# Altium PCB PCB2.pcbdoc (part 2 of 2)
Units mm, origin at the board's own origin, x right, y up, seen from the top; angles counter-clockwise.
Board outline 201.42 x 135 mm, 2 copper layers (Top Layer, Bottom Layer); 117 components, 69 nets, 446 pads, 480 vias.
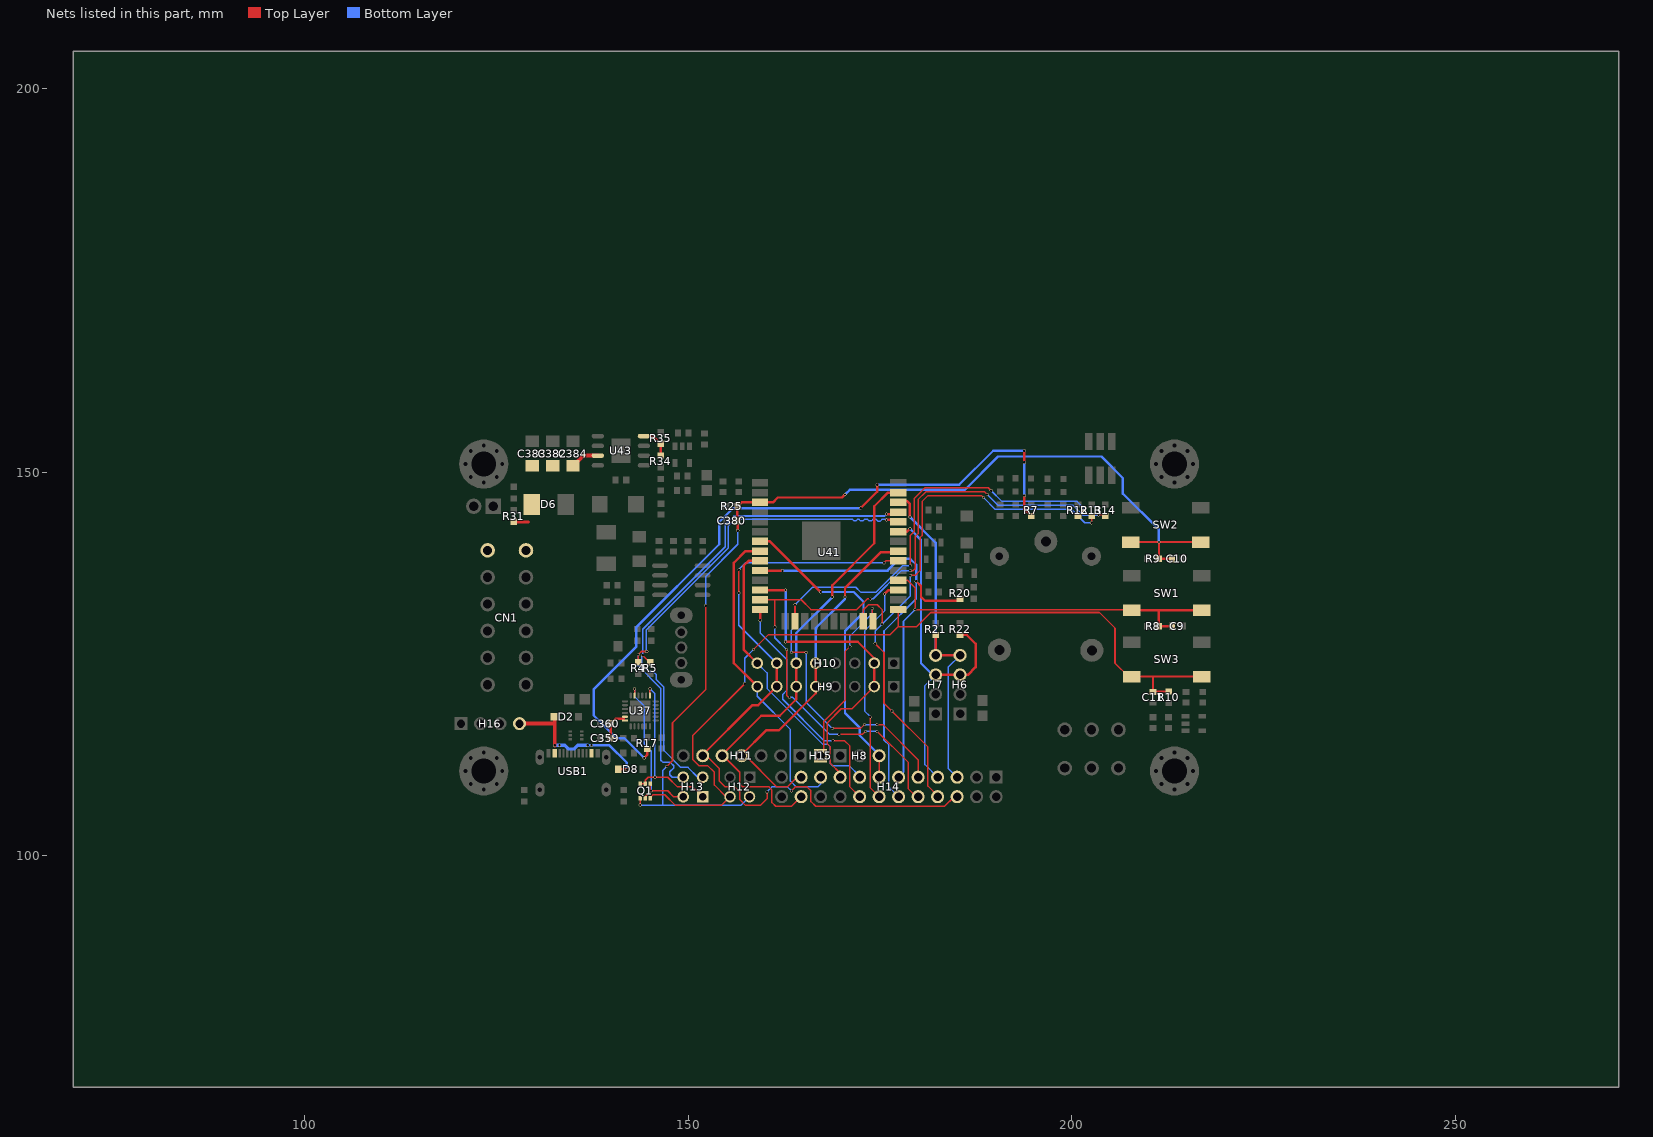
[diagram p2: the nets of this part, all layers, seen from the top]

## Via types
v1: diameter 0.4, hole 0.3, Top Layer to Bottom Layer, 480 vias

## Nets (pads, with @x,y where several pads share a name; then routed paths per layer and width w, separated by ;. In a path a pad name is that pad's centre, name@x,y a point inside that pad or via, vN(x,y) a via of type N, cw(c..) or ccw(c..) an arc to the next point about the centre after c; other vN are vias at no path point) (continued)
DTR: H13.2 Q1.1 Q1.5 U37.23 | length 21.9
  Top Layer w0.2: U37.23@143.014,120.872 v1(143.014,121.761) ; Q1.5@144.399,107.508 144.399,107.696 v1(145.161,108.458) ; Q1.1@145.049,109.408 145.049,108.458 v1(145.161,108.458) ; H13.2@149.352,107.696 148.082,107.696 147.32,108.458 v1(145.161,108.458)
  Bottom Layer w0.2: v1(143.014,121.761) 143.014,120.765 144.272,119.507 144.272,114.554 145.161,113.665 v1(145.161,108.458)
EN: C10.1 C380.1 H12.2 Q1.4 R9.1 R25.2 SW2.3 SW2.4 U41.3 | length 136.1
  Top Layer w0.2: v1(143.749,106.619) Q1.4@143.749,107.508 ; v1(147.193,111.633) 147.955,112.395 147.955,117.348 152.273,121.666 v1(152.273,132.588)
  Top Layer w0.312: v1(156.453,142.367) 156.453,143.586 C380.1@156.402,143.637 156.402,145.489 R25.2@156.455,145.542 156.961,146.048 U41.3@159.364,146.048 161.034,146.048 161.671,146.685 170.055,146.685 v1(170.434,147.064) ; SW2.3@207.667,140.879 v1(211.346,140.879) ; C10.1@213.041,138.684 R9.1@211.319,138.684 211.346,138.71 v1(211.346,140.879) ; SW2.4@216.767,140.879 v1(211.346,140.879)
  Bottom Layer w0.2: v1(143.749,106.619) 143.815,106.553 146.671,106.553 ; v1(147.193,111.633) 146.671,111.111 146.671,106.553 ; v1(152.273,132.588) 152.273,136.398 156.453,140.578 v1(156.453,142.367) ; H12.2@157.988,107.696 156.845,106.553 146.671,106.553
  Bottom Layer w0.312: v1(170.434,147.064) 171.071,147.701 186.055,147.701 190.373,152.019 203.835,152.019 206.629,149.225 206.629,147.193 211.328,142.494 v1@211.328,140.843
FB: R34.2 R35.1 U43.4 | length 4.2
  Top Layer w0.312: U43.4@144.224,154.686 145.424,154.686 R35.1@146.431,153.679 R34.2@146.431,152.137
GND: 
IO0: C11.1 H12.4 Q1.6 R10.1 SW3.3 SW3.4 U41.25 | length 109.9
  Top Layer w0.2: Q1.6@145.049,107.508 145.049,107.584 145.415,107.95 146.939,107.95 148.336,106.553 154.305,106.553 H12.4@155.448,107.696 154.94,107.696 153.416,109.22 153.416,110.871 152.527,111.76 151.384,111.76 150.622,112.522 150.622,115.697 v1(157.353,122.428) ; v1(158.496,126.873) 160.401,128.778 176.276,128.778 177.364,129.866 ; U41.25@177.364,132.078 177.364,129.866 ; SW3.3@207.794,123.353 207.355,123.353 205.613,125.095 205.613,129.667 203.581,131.699 181.61,131.699 179.777,129.866 177.364,129.866
  Top Layer w0.312: SW3.3@207.794,123.353 210.614,123.353 ; R10.1@212.598,121.403 210.619,121.403 C11.1@210.566,121.35 210.566,123.305 210.614,123.353 ; SW3.4@216.894,123.353 210.614,123.353
  Bottom Layer w0.2: v1(157.353,122.428) 157.353,125.73 v1(158.496,126.873)
IO2: H15.1 U41.24 | length 23.7
  Top Layer w0.2: H15.1@167.259,113.03 167.64,113.411 167.64,117.475 170.434,120.269 170.434,126.619 v1(171.069,127.254) ; v1(173.99,132.207) 173.99,130.647 U41.24@174.079,130.558
  Bottom Layer w0.2: v1(171.069,127.254) 171.069,128.651 173.99,131.572 v1(173.99,132.207)
IO12: H14.16 U41.14 | length 31.7
  Top Layer w0.2: v1(168.846,114.998) 170.37,114.998 171.069,114.3 171.069,108.966 H14.16@172.339,107.696
  Top Layer w0.312: U41.14@159.364,132.078 159.385,132.057 v1(159.385,130.683)
  Bottom Layer w0.2: v1(159.385,130.683) 159.385,129.032 162.814,125.603 162.814,121.539 162.306,121.031 162.306,120.396 167.703,114.998 v1(168.846,114.998)
IO16: H14.14 U41.27 | length 30.3
  Top Layer w0.2: v1(173.736,118.11) 173.736,108.839 H14.14@174.879,107.696
  Top Layer w0.312: v1(175.586,134.11) 176.094,134.618 U41.27@177.364,134.618
  Bottom Layer w0.2: v1(173.736,118.11) 172.974,118.872 172.974,129.286 175.586,131.898 v1(175.586,134.11)
IO35: H8.3 H14.13 U41.7 | length 42.4
  Top Layer w0.2: H14.13@174.879,110.236 H8.3@174.879,113.157
  Top Layer w0.312: U41.7@159.364,140.968 160.657,140.968 v1(167.259,134.366)
  Bottom Layer w0.312: v1(167.259,134.366) 171.577,134.366 172.847,133.096 172.847,131.699 170.434,129.286 170.434,118.618 172.339,116.713 172.339,115.697 H8.3@174.879,113.157
LED_B: H14.10 R14.1 U41.13 | length 96.3
  Top Layer w0.2: U41.13@159.364,133.348 161.29,133.348 ; v1(161.29,129.794) 161.29,133.348 ; v1(162.814,126.873) 162.814,120.904 163.068,120.65 v1(163.195,120.65) ; v1(169.672,115.824) 172.72,115.824 v1(173.101,116.205) ; v1(173.736,133.475) 173.353,133.475 171.958,132.08 165.989,132.08 164.721,133.348 161.29,133.348 ; v1(174.625,116.205) 178.689,112.141 178.689,108.712 179.705,107.696 H14.10@179.959,107.696 ; v1(178.943,137.16) 179.324,137.16 179.578,137.414 179.578,141.605 179.959,141.986 179.959,146.431 180.975,147.447 188.595,147.447 v1(188.976,147.066) ; v1(203.454,144.408) 204.216,144.408 R14.1@204.343,144.281
  Bottom Layer w0.2: v1(161.29,129.794) 161.29,128.397 v1(162.814,126.873) ; v1(163.195,120.65) 163.576,120.65 168.402,115.824 v1(169.672,115.824) ; v1(173.101,116.205) v1(174.625,116.205) ; v1(173.736,133.475) 174.115,133.475 177.8,137.16 v1(178.943,137.16) ; v1(188.976,147.066) 190.373,145.669 200.152,145.669 201.422,144.399 v1@203.454,144.399
LED_G: H14.8 R13.1 U41.23 | length 75.9
  Top Layer w0.2: U41.23@172.809,130.558 172.809,132.042 173.482,132.715 174.625,132.715 175.26,132.08 v1(175.26,130.175) ; v1(174.371,127.635) 175.514,126.492 175.514,119.888 v1(176.53,118.872) 181.229,114.173 181.229,109.093 182.499,107.823 H14.8@182.499,107.696 ; v1(178.943,136.525) 179.578,136.525 180.213,137.16 180.213,141.478 180.467,141.732 180.467,146.177 181.229,146.939 188.214,146.939 v1(188.468,146.685) ; v1(202.565,143.392) R13.1@202.565,144.281
  Bottom Layer w0.2: v1(174.371,127.635) 174.371,129.286 v1(175.26,130.175) 178.943,133.858 v1(178.943,136.525) ; v1(188.468,146.685) 189.992,145.161 199.898,145.161 201.667,143.392 v1(202.565,143.392)
LED_R: H14.9 R12.1 U41.16 | length 89.2
  Top Layer w0.2: v1(163.449,126.492) v1(165.383,126.492) ; v1(168.783,116.586) 172.466,116.586 v1(172.974,117.094) ; v1(174.625,117.094) 175.387,117.094 179.959,112.522 H14.9@179.959,110.236 ; v1(178.943,137.795) 178.943,141.732 179.451,142.24 179.451,146.558 180.848,147.955 189.103,147.955 v1(189.484,147.574) ; R12.1@200.787,144.281 v1(201.676,145.17)
  Top Layer w0.312: U41.16@163.919,130.558 v1(163.919,132.717)
  Bottom Layer w0.2: v1(163.449,126.492) 163.449,129.413 163.919,129.883 v1(163.919,132.717) 166.203,135.001 171.831,135.001 172.466,134.366 174.498,134.366 177.927,137.795 v1(178.943,137.795) ; v1(165.383,126.492) 165.383,119.986 v1(168.783,116.586) ; v1(172.974,117.094) v1(174.625,117.094) ; v1(189.484,147.574) 190.881,146.177 200.669,146.177 v1(201.676,145.17)
MISO: H9.5 H10.5 H11.4 H14.21 U41.31 | length 46.6
  Top Layer w0.2: H11.4@156.972,113.157 157.353,113.157 161.544,108.966 162.918,108.966 164.188,110.236 H14.21@164.719,110.236
  Top Layer w0.312: H11.4@156.972,113.157 160.147,116.332 161.788,116.332 166.624,121.168 H9.5@166.624,122.047 H10.5@166.624,125.095 ; v1(170.434,133.731) 170.434,134.874 175.133,139.573 177.239,139.573 U41.31@177.364,139.698
  Bottom Layer w0.312: H10.5@166.624,125.73 166.624,129.667 170.434,133.477 v1(170.434,133.731)
MOSI: H9.6 H10.6 H11.5 H14.22 U41.37 | length 60.7
  Top Layer w0.2: H11.5@154.432,113.157 156.718,110.871 156.718,109.347 157.099,108.966 160.528,108.966 160.909,108.585 160.909,106.934 161.398,106.445 163.468,106.445 H14.22@164.719,107.696
  Top Layer w0.312: H11.5@154.432,113.157 159.512,118.237 161.925,118.237 164.084,120.396 H9.6@164.084,122.047 H10.6@164.084,125.095 ; v1(168.783,133.731) 168.783,135.255 174.244,140.716 174.244,145.542 176.022,147.32 177.362,147.32 U41.37@177.364,147.318
  Bottom Layer w0.312: H10.6@164.084,125.73 164.084,129.032 v1(168.783,133.731)
RELAY: H14.12 R20.1 U41.10 | length 61.7
  Top Layer w0.312: U41.10@159.364,137.158 v1(162.285,137.158) ; v1(179.707,135.763) 180.34,135.13 180.34,133.731 180.848,133.223 185.039,133.223 185.302,133.486 R20.1@185.42,133.486
  Bottom Layer w0.2: H14.12@177.419,107.696 176.149,108.966 176.149,114.427 175.514,115.062 175.514,129.286 179.707,133.479 v1(179.707,135.763)
  Bottom Layer w0.312: v1(162.285,137.158) 175.977,137.158 177.503,138.684 178.943,138.684 179.707,137.92 v1(179.707,135.763)
RFID0_SS: H9.8 H14.19 U41.8 | length 40.6
  Top Layer w0.312: H9.8@158.623,122.428 155.956,125.095 155.956,138.176 157.478,139.698 U41.8@159.364,139.698 ; H9.8@158.75,122.555 H9.8@159.004,122.555
  Bottom Layer w0.2: H9.8@159.004,122.047 159.004,120.777 163.322,116.459 163.322,109.728 164.084,108.966 166.878,108.966 167.259,109.347 H14.19@167.259,110.236
RFID1_SS: H10.8 H14.15 U41.9 | length 37.9
  Top Layer w0.312: H10.8@159.004,125.095 157.226,126.873 157.226,137.795 157.859,138.428 U41.9@159.364,138.428
  Bottom Layer w0.2: H10.8@159.004,125.095 160.274,123.825 160.274,121.793 167.513,114.554 168.148,114.554 168.529,114.173 168.529,112.014 168.783,111.76 170.942,111.76 172.339,110.363 H14.15@172.339,110.236
RFID_RST: H9.2 H10.2 H14.17 U41.12 | length 41.4
  Top Layer w0.2: H14.17@169.799,110.236 169.799,110.744 168.529,112.014 168.529,114.173 168.148,114.554 168.148,117.348 169.953,119.153 171.35,119.153 H9.2@174.244,122.047
  Top Layer w0.312: U41.12@159.364,134.618 v1(162.689,134.618) ; v1(162.687,127.889) 172.085,127.889 H10.2@174.244,125.73 ; H9.2@174.244,122.047 H10.2@174.244,125.095
  Bottom Layer w0.312: v1(162.687,127.889) 162.689,127.891 v1(162.689,134.618)
RTS: H13.1 Q1.2 Q1.3 U37.19 | length 22.5
  Top Layer w0.2: Q1.3@143.749,109.408 Q1.2@144.399,109.408 144.399,109.855 144.78,110.236 v1(145.669,110.236) 147.32,110.236 148.59,108.966 150.622,108.966 H13.1@151.892,107.696 ; U37.19@145.014,120.872 v1(145.014,121.761)
  Bottom Layer w0.2: v1(145.014,121.761) 145.669,121.106 v1(145.669,110.236)
RX: H13.3 R5.2 U41.35 | length 66.5
  Top Layer w0.2: v1(144.072,126.111) 144.97,125.213 R5.2@145.034,125.213
  Top Layer w0.312: v1(175.84,144.524) 176.898,144.524 177.152,144.778 U41.35@177.364,144.778
  Bottom Layer w0.2: v1(144.072,126.111) 144.072,129.525 154.813,140.266 154.813,143.129 155.956,144.272 175.588,144.272 v1(175.84,144.524) ; v1@144.073,126.11 143.971,126.007 143.971,124.88 144.839,124.011 145.44,124.011 145.836,123.615 145.836,122.953 146.831,121.959 146.831,113.704 149.029,111.506 149.987,111.506 151.257,110.236 H13.3@151.892,110.236
SCK: H9.7 H10.7 H11.6 H14.6 U41.30 | length 93.6
  Top Layer w0.2: H11.6@151.892,113.03 152.4,113.03 154.051,111.379 154.051,109.728 154.813,108.966 156.083,108.966 156.718,108.331 156.718,107.315 157.48,106.553 159.385,106.553 160.274,107.442 v1(160.274,108.331) ; v1(156.591,134.239) v1(156.591,137.287) ; v1(163.449,108.458) 163.957,108.966 165.481,108.966 165.989,108.458 165.989,107.061 166.605,106.445 183.407,106.445 184.658,107.696 H14.6@185.039,107.696 ; v1(175.514,138.176) 175.766,138.428 U41.30@177.364,138.428
  Top Layer w0.312: H11.6@151.892,113.157 158.369,119.634 159.131,119.634 H9.7@161.544,122.047 H10.7@161.544,125.095
  Bottom Layer w0.2: v1(156.591,134.239) 156.591,130.048 H10.7@161.544,125.095 ; v1(156.591,137.287) 157.48,138.176 v1(175.514,138.176) ; v1(160.274,108.331) 160.909,108.966 162.941,108.966 v1(163.449,108.458)
SCL: H6.4 H7.4 H14.5 R21.2 U41.36 | length 45.7
  Top Layer w0.312: U41.36@177.364,146.048 177.493,146.177 178.562,146.177 178.888,145.851 v1(178.888,144.143) ; R21.2@182.245,128.787 H7.4@182.245,126.111 H6.4@185.42,126.111
  Bottom Layer w0.2: H14.5@185.039,110.236 183.896,111.379 183.896,124.587 H6.4@185.42,126.111
  Bottom Layer w0.312: v1(178.888,144.143) 182.245,140.786 H7.4@182.245,126.111
SDA: H6.3 H7.3 H14.7 R22.2 U41.33 | length 48.1
  Top Layer w0.312: U41.33@177.364,142.238 178.507,142.238 v1(178.888,142.619) ; H7.3@182.245,123.571 H6.3@185.42,123.571 186.436,123.571 187.452,124.587 187.452,127.635 186.3,128.787 R22.2@185.42,128.787
  Bottom Layer w0.2: H7.3@182.245,123.571 180.848,122.174 180.848,111.887 H14.7@182.499,110.236
  Bottom Layer w0.312: v1(178.888,142.619) 180.34,141.167 180.34,125.095 181.864,123.571 H7.3@182.245,123.571
SW: C9.1 H14.11 R8.1 SW1.3 SW1.4 U41.28 | length 69.3
  Top Layer w0.2: U41.28@177.364,135.888 178.564,135.888 179.578,134.874 v1(179.578,132.08) 207.703,132.08 SW1.3@207.794,131.989
  Top Layer w0.312: SW1.3@207.794,131.989 211.303,131.989 ; C9.1@213.041,129.921 R8.1@211.319,129.921 211.319,131.973 211.303,131.989 ; SW1.4@216.894,131.989 211.303,131.989
  Bottom Layer w0.2: H14.11@177.419,110.236 178.054,110.871 178.054,130.556 v1(179.578,132.08)
TX: H13.4 R4.2 U41.34 | length 66.7
  Top Layer w0.2: R4.2@143.51,125.213 v1(143.51,126.238) 143.891,126.619 v1(144.599,126.619)
  Top Layer w0.312: v1(175.84,143.762) 176.898,143.762 177.152,143.508 U41.34@177.364,143.508
  Bottom Layer w0.2: v1(143.51,126.238) 143.51,124.714 146.431,121.793 146.431,112.452 146.726,112.157 147.685,112.157 148.112,111.73 148.112,111.447 147.601,110.936 147.601,110.564 147.929,110.236 H13.4@149.352,110.236 ; v1(144.599,126.619) 144.526,126.692 144.526,129.413 155.213,140.1 155.213,142.963 156.122,143.872 171.361,143.872 171.605,143.629 171.864,143.629 172.072,143.837 172.265,143.837 172.465,143.637 172.77,143.637 172.97,143.837 173.364,143.837 173.564,143.637 173.882,143.637 174.094,143.849 174.473,143.849 174.704,143.618 175.042,143.618 175.296,143.872 175.73,143.872 v1(175.84,143.762)
USB5V: D2.1 D8.1 H16.4 USB1.2 USB1.11 | length 21.1
  Top Layer w0.312: D8.1@140.884,111.252 v1(141.986,111.252)
  Top Layer w0.5: H16.4@128.016,117.221 132.579,117.221 132.601,117.243 ; D2.1@132.502,118.11 132.601,118.011 132.601,117.243 ; v1(132.601,114.389) 132.601,117.243
  Bottom Layer w0.312: v1(136.893,114.389) v1(137.401,114.389) 139.738,114.389 141.986,112.141 v1(141.986,111.252)
  Bottom Layer w0.44: v1(132.601,114.389) v1(133.236,114.389) 133.896,114.389 134.366,113.919 135.128,113.919 135.598,114.389 v1(136.893,114.389)
VCC: C382.2 C383.2 C384.2 CN1.1 D6.2 R31.1 U43.7 | length 5.7
  Top Layer w0.4: R31.1@127.254,143.519 129.159,143.519
  Top Layer w0.5: C384.2@135.001,150.807 136.34,152.146 U43.7@138.224,152.146
VDD: C359.2 C360.2 R7.1 R17.1 U37.5 U37.6 | length 99.9
  Top Layer w0.312: v1(140.654,115.316) C359.2@139.892,115.316 C360.2@139.892,117.221 140.527,117.856 141.605,117.856 ; v1(144.272,112.743) 144.653,113.124 R17.1@144.653,113.928 ; v1(172.466,145.288) 174.625,147.447 v1(174.625,148.336) ; v1(193.802,146.948) 193.802,145.17 R7.1@194.691,144.281 ; v1(193.802,151.257) v1(193.802,152.781)
  Bottom Layer w0.312: v1(144.272,112.743) 141.699,115.316 v1(140.654,115.316) 137.668,118.302 137.668,121.666 143.256,127.254 143.256,129.794 154.051,140.589 154.051,143.51 155.829,145.288 v1(172.466,145.288) ; v1(174.625,148.336) 185.293,148.336 189.738,152.781 v1(193.802,152.781) ; v1(193.802,146.948) v1(193.802,151.257)
pads on no net: C1.2 C2.2 C3.2 C6.1 C9.2 C10.2 C11.2 C351.1 C352.1 C353.1 C354.1 C355.1 C356.1 C357.1 C358.1 C359.1 C360.1 C361.1 C362.1 C363.2 C364.2 C369.1 C370.1 C371.1 C372.1 C373.1 C374.1 C375.1 C376.1 C377.2 C378.2 C379.2 C380.2 C382.1 C383.1 C384.1 C385.1 C386.1 C387.1 C388.1 C390.1 CN1.2 D1.2 D5.2 D6.1 H1.1 H2.1 H3.1 H4.1 H6.1 H7.1 H8.1 H9.3 H9.4 H10.3 H10.4 H11.2 H12.3 H14.3 H14.4 H16.1 H17.2 LED1.4 LED1.5 LED1.6 LED白.1 LED红.2 LED绿.1 LED蓝.2 Q2.2 R1.2 R2.2 R15.2 R19.2 R32.1 R35.2 SW1.1 SW1.2 SW2.1 SW2.2 SW3.1 SW3.2 U31.2 U31.4 U34.2 U36.3 U36.4 U36.5 U37.1 U37.2 U37.10 U37.11 U37.12 U37.13 U37.14 U37.15 U37.17 U37.18 U37.22 U37.24 U37.25 U40.2 U40.4 U41.1 U41.4 U41.5 U41.15 U41.17 U41.18 U41.19 U41.20 U41.21 U41.22 U41.32 U41.38 U41.39 U42.2 U42.4 U43.2 U43.3 U43.5 U43.6 U43.9 USB1.1 USB1.3 USB1.9 USB1.12 USB1.13 USB1.14
copper on no net: | length 8.8
  Top Layer w0.2: v1(135.128,116.967) 136.271,116.967 136.652,117.348 136.652,118.491 138.303,120.142 140.482,120.142 v1(141.002,119.622) 141.764,119.622
  other v1: 137.795,106.934 181.229,106.934 168.529,107.061 126.492,107.188 145.923,107.315 209.804,107.315 215.9,107.315 153.543,107.569 150.622,107.696 134.239,108.458 172.974,108.966 179.33,108.966 180.6,108.966 145.923,109.093 147.353,109.144 150.622,109.658 159.258,109.855 135.58,109.911 148.209,110.744 128.27,110.871 161.289,111.252 163.83,111.252 160.02,111.506 168.148,111.506 157.734,111.633 172.974,111.633 174.244,111.633 217.551,111.633 179.324,112.141 182.118,112.522 190.498,112.522 177.038,112.649 147.066,112.776 127.635,113.411 119.761,114.173 175.312,114.407 186.944,114.427 165.862,114.554 216.662,114.554 134.62,114.681 172.085,114.681 126.873,114.808 154.813,114.808 131.318,114.935 157.48,114.935 174.498,114.935 179.197,114.935 213.995,115.189 148.59,115.57 133.223,115.697 183.134,115.697 152.781,115.824 185.166,115.824 188.214,115.824 124.206,115.951 162.687,116.078 190.373,116.205 130.556,116.459 159.004,116.459 167.005,116.459 177.038,116.586 141.487,116.655 153.67,116.713 156.898,116.907 169.418,117.221 215.983,117.284 151.394,117.602 154.491,117.608 142.748,117.844 144.78,117.844 172.847,117.856 126.746,117.983 139.192,118.058 174.788,118.066 134.112,118.11 150.114,118.364 165.1,118.364 147.701,118.618 152.654,118.745 143.764,118.86 158.877,118.872 206.883,118.872 130.302,119.38 156.718,119.38 125.857,119.507 142.748,119.876 144.78,119.876 131.572,120.015 168.91,120.269 173.99,120.269 174.788,120.269 171.45,120.523 148.082,120.65 152.527,120.904 140.843,121.031 149.86,121.031 208.153,121.031 155.321,121.539 206.375,121.793 142.113,121.92 120.904,122.301 137.795,123.063 153.67,123.19 187.96,123.317 159.131,123.444 134.62,123.571 162.179,123.571 163.418,123.571 164.734,123.571 165.989,123.571 167.259,123.571 169.291,123.571 171.704,123.571 173.482,123.698 179.197,123.698 126.492,123.825 142.494,123.825 146.798,123.84 211.455,124.333 120.777,124.46 138.557,124.46 186.69,124.952 146.798,125.401 207.273,125.603 132.842,125.73 179.197,125.767 216.408,125.857 156.718,125.984 210.947,125.984 154.051,126.365 174.498,126.619 171.831,126.746 167.227,126.873 169.291,126.873 176.657,126.873 186.69,127.099 164.973,127.254 126.238,127.508 127.842,127.508 142.24,127.508 157.861,127.508 181.102,127.762 183.87,127.762 173.609,127.889 137.795,127.954 147.193,128.143 177.038,128.143 179.324,128.778 155.321,128.905 135.89,129.159 154.051,129.261 146.431,129.54 216.662,129.54 187.325,129.794 181.229,130.429 138.684,130.556 158.369,130.556 191.77,130.556 201.041,130.556 121.031,130.683 179.451,130.683 160.401,130.81 131.448,130.985 126.746,131.191 155.321,132.004 164.721,132.16 166.37,132.588 142.113,132.715 149.098,133.008 137.541,133.096 189.137,133.477 191.516,133.477 211.328,133.731 154.051,133.798 142.113,134.057 216.894,134.239 163.703,134.366 155.321,134.685 200.533,134.747 204.868,134.747 120.987,134.874 126.766,134.874 131.699,134.874 174.371,135.001 181.229,135.509 189.484,135.89 212.344,135.997 184.15,136.525 168.314,136.6 163.195,136.652 191.008,136.779 141.732,137.033 154.051,137.032 155.321,137.244 131.699,137.541 148.082,137.535 181.102,137.541 136.719,137.774 165.188,138.886 167.347,138.886 169.506,138.886 161.29,138.938 173.355,138.938 205.74,138.938 134.112,139.065 157.734,139.065 120.523,139.192 141.36,139.269 184.531,139.328 156.337,139.573 157.48,140.589 175.387,140.69 137.16,140.716 172.212,140.843 165.188,141.045 167.347,141.045 169.506,141.045 200.533,141.224 141.919,141.378 190.119,141.478 155.829,141.605 181.991,141.823 171.45,142.113 212.598,142.113 149.86,142.367 162.052,142.367 175.387,142.367 192.974,142.37 134.747,142.621 147.193,142.748 189.103,142.748 205.74,142.775 157.734,143.129 215.982,143.129 165.188,143.204 167.347,143.204 169.506,143.204 184.531,143.256 144.272,143.51 136.271,143.637 150.524,143.667 181.229,143.885 181.991,143.885 119.888,144.018 211.43,144.424 149.098,144.653 154.178,144.78 161.716,144.78 169.545,144.78 173.482,145.034 175.514,145.288 188.468,145.415 150.622,145.542 136.525,145.915 186.182,145.923 213.617,146.301 205.74,146.557 161.163,147.066 144.78,147.193 140.335,147.447 208.534,147.447 202.819,147.574 204.47,147.574 119.634,147.701 157.734,148.082 207.748,148.131 217.275,148.131 161.544,148.336 165.264,148.336 167.894,148.336 171.273,148.336 189.914,148.323 201.041,148.343 132.842,148.463 145.288,148.59 136.525,149.352 150.876,149.479 154.305,149.987 206.883,150.114 180.594,150.241 184.023,150.241 140.236,150.281 193.04,150.368 142.875,150.495 149.288,151.061 201.041,151.13 192.278,151.257 140.335,151.511 142.113,151.511 156.21,151.765 205.105,151.765 183.642,152.019 149.288,152.075 130.689,152.4 133.494,152.4 208.026,152.527 141.224,152.781 145.415,152.908 154.378,153.006 151.06,153.225 182.499,153.416 156.464,153.543 120.269,153.924 140.335,154.051 142.113,154.051 208.534,154.051 147.382,154.305 155.194,154.559 126.238,154.686 187.958,154.813 193.554,154.813 196.977,154.813 141.605,155.194 200.914,155.194 136.779,155.321

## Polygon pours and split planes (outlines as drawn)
USB5V on Top Layer (solid, remove dead copper): 132.282,112.803 132.896,112.803 132.896,114.797 132.282,114.797
USB5V on Bottom Layer (solid, remove dead copper, pour order 60): 132.207,114.046 133.604,114.046 133.604,114.808 132.207,114.808
USB5V on Top Layer (solid, remove dead copper, pour order 2): 132.282,114.116 133.516,114.116 133.516,114.808 132.282,114.808
+5V on Bottom Layer (solid, remove dead copper, pour order 62): 139.917,128.115 141.719,128.115 141.719,129.291 139.917,129.291
USB5V on Top Layer (solid, remove dead copper, pour order 4): 136.597,114.12 137.703,114.12 137.703,114.71 136.597,114.71
$1N9535 on Bottom Layer (solid, remove dead copper, pour order 64): 200.787,109.855 204.216,109.855 204.216,120.65 200.787,120.65
VDD on Top Layer (solid, remove dead copper, pour order 6): 141.224,117.348 142.24,117.348 142.24,118.364 141.224,118.364
$1N9535 on Bottom Layer (solid, remove dead copper, pour order 66): 194.437,119.908 198.882,119.908 198.882,143.256 194.437,143.256
$1N9535 on Bottom Layer (solid, remove dead copper, pour order 68): 194.437,119.507 204.216,119.507 204.216,123.825 194.437,123.825
VCC on Top Layer (solid, remove dead copper, pour order 8): 122.301,138.43 130.683,138.43 130.683,141.351 122.301,141.351
3V3 on Bottom Layer (solid, remove dead copper, pour order 70): 213.069,119.26 214.484,119.26 214.484,120.65 213.069,120.65
VCC on Top Layer (solid, remove dead copper, pour order 10): 128.524,140.589 130.683,140.589 130.683,147.193 128.524,147.193
$1N9531 on Bottom Layer (solid, remove dead copper, pour order 72): 196.977,109.855 200.406,109.855 200.406,117.983 196.977,117.983
$1N9540 on Bottom Layer (solid, remove dead copper, pour order 74): 204.597,109.855 207.518,109.855 207.518,117.983 204.597,117.983
VCC on Top Layer (solid, remove dead copper, pour order 12): 128.524,147.193 130.645,147.193 130.645,151.55 128.524,151.55
3.3_SENSOR on Bottom Layer (solid, remove dead copper, pour order 76): 183.162,133.747 184.15,133.747 184.15,135.003 183.162,135.003
VCC on Top Layer (solid, remove dead copper, pour order 14): 128.501,149.836 135.833,149.836 135.833,151.55 128.501,151.55
+5V on Top Layer (solid, remove dead copper, pour order 16): 139.954,127.58 141.685,127.58 141.685,129.286 139.954,129.286
3.3_SENSOR on Bottom Layer (solid, remove dead copper, pour order 78): 183.388,129.794 184.658,129.794 184.658,130.81 183.388,130.81
+5V on Bottom Layer (solid, remove dead copper, pour order 80): 209.169,115.824 210.058,115.824 210.058,117.856 209.169,117.856
3.3_SENSOR on Top Layer (solid, remove dead copper, pour order 18): 180.276,119.444 180.276,121.602 178.752,121.602 178.752,119.444
3V3 on Top Layer (solid, remove dead copper, pour order 20): 147.615,138.844 149.203,138.844 149.203,140.335 147.615,140.335
$1N9540 on Top Layer (solid, remove dead copper, pour order 22): 193.548,105.972 207.422,105.972 207.422,109.474 193.548,109.474
+5V on Bottom Layer (solid, remove dead copper, pour order 82): 150.241,138.303 151.384,138.303 151.384,139.446 150.241,139.446
$1N9540 on Top Layer (solid, remove dead copper, pour order 24): 188.595,124.079 195.58,124.079 195.58,129.413 188.595,129.413
3V3 on Bottom Layer (solid, remove dead copper, pour order 84): 148.297,138.811 149.479,138.811 149.479,140.335 148.297,140.335
$1N9540 on Top Layer (solid, remove dead copper, pour order 26): 192.151,103.926 196.596,103.926 196.596,129.413 192.151,129.413
3V3 on Bottom Layer (solid, remove dead copper, pour order 86): 151.257,151.003 152.146,151.003 152.146,152.527 151.257,152.527
$1N9540 on Top Layer (solid, remove dead copper, pour order 28): 204.597,109.012 207.422,109.012 207.422,117.983 204.597,117.983
3V3 on Bottom Layer (solid, remove dead copper, pour order 88): 154.432,151.003 155.194,151.003 155.194,152.4 154.432,152.4
$1N9535 on Top Layer (solid, remove dead copper, pour order 30): 200.787,109.855 204.216,109.855 204.216,117.983 200.787,117.983
$1N9531 on Top Layer (solid, remove dead copper, pour order 32): 196.977,109.855 200.406,109.855 200.406,118.491 196.977,118.491
$1N9531 on Top Layer (solid, remove dead copper, pour order 34): 196.977,117.475 200.406,117.475 200.406,129.413 196.977,129.413
+5V on Bottom Layer (solid, remove dead copper, pour order 90): 183.896,145.288 185.293,145.288 185.293,146.685 183.896,146.685
$1N9531 on Top Layer (solid, remove dead copper, pour order 36): 196.977,124.46 204.47,124.46 204.47,129.413 196.977,129.413
3V3 on Top Layer (solid, remove dead copper, pour order 38): 213.069,119.26 214.484,119.26 214.484,120.65 213.069,120.65
3.3_SENSOR on Top Layer (solid, remove dead copper, pour order 40): 182.245,133.731 184.15,133.731 184.15,135.003 182.245,135.003
3.3_SENSOR on Top Layer (solid, remove dead copper, pour order 42): 183.388,129.794 184.658,129.794 184.658,130.81 183.388,130.81
3V3 on Top Layer (solid, remove dead copper, pour order 44): 151.257,151.003 152.146,151.003 152.146,152.527 151.257,152.527
3V3 on Top Layer (solid, remove dead copper, pour order 46): 154.432,151.003 155.194,151.003 155.194,152.4 154.432,152.4
+5V on Top Layer (solid, remove dead copper, pour order 48): 183.896,144.78 185.293,144.78 185.293,146.685 183.896,146.685
USB5V on Top Layer (solid, remove dead copper, pour order 50): 131.953,116.967 132.969,116.967 132.969,118.618 131.953,118.618
USB5V on Top Layer (solid, remove dead copper, pour order 52): 136.597,114.046 137.795,114.046 137.795,114.71 136.597,114.71
USB5V on Top Layer (solid, remove dead copper, pour order 54): 137.101,112.802 137.703,112.802 137.703,114.71 137.101,114.71
USB5V on Bottom Layer (solid, remove dead copper, pour order 92): 136.525,114.046 137.795,114.046 137.795,114.808 136.525,114.808
CP210-5V on Top Layer (solid, remove dead copper, pour order 56): 142.367,116.407 143.154,116.407 143.154,117.348 142.367,117.348
no net on Top Layer (solid, remove dead copper, pour order 58): 97.79,76.2 264.922,76.2 264.922,175.133 97.79,175.133
no net on Bottom Layer (solid, remove dead copper, pour order 94): 76.2,82.423 247.015,82.423 247.015,198.501 76.2,198.501

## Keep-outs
Board Outline Layer:
  lines w0.254: 118.364,110.045 ccw(c122.364,110.045) 122.364,106.045 214.364,106.045 ccw(c214.364,110.045) 218.364,110.045 218.364,152.045 ccw(c214.364,152.045) 214.364,156.045 122.364,156.045 ccw(c122.364,152.045) 118.364,152.045 118.364,110.045
Multi-Layer:
  region: 157.099,149.523 180.048,149.523 180.048,157.226 157.099,157.226

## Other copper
Top Layer:
  drawing of 452 lines, arcs and shapes, not listed
Bottom Layer:
  drawing of 163 lines, arcs and shapes, not listed

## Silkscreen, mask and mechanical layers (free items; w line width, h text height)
Top Silkscreen Layer:
  drawing of 195 lines, arcs and shapes, not listed
  text "RELA Y\N" at 191.262,150.114 h1.1 r90
  text "POWER" at 193.421,150.114 h1.5 r90
  text "USB" at 195.453,150.114 h1.5 r90
  text "SENSOR" at 197.485,149.987 h1.5 r90
  text "5V>3V3" at 199.644,149.987 h1.5 r90
  text "RGBLED" at 201.041,146.685 h1.5
  text "GND" at 120.904,142.748 h1
  text "ADC" at 123.825,142.748 h1
  text "EN" at 208.407,142.367 h1.5 r90
  text "EN" at 217.551,142.367 h1.5 r90
  text "12V" at 133.35,138.938 h1.5
  text "GND" at 133.477,135.509 h1.5
  text "SW" at 208.534,133.35 h1.5 r90
  text "SW" at 217.805,133.35 h1.5 r90
  text "CAN_H" at 133.35,132.334 h1.5
  text "CAN_L" at 133.35,128.524 h1.5
  text "RFID" at 172.974,127.762 h1
  text "ON" at 151.892,127.508 h1.5
  text "SCL" at 187.198,127.127 h1 r270
  text "SCK" at 160.528,126.746 h1
  text "MOSI" at 163.068,126.746 h1
  text "MISO" at 165.862,126.746 h1
  text "GND" at 170.434,126.746 h1
  text "3V3" at 175.768,126.746 h1
  text "RST" at 173.101,126.619 h1
  text "SCL" at 180.467,125.349 h1 r90
  text "CAN_H" at 133.477,125.095 h1.5
  text "OFF" at 151.892,124.968 h1.5
  text "RFID1" at 154.813,124.587 h1
  text "IO0" at 208.534,124.587 h1.5 r90
  text "IO0" at 217.678,124.587 h1.5 r90
  text "SDA" at 187.198,124.333 h1 r270
  text "SDA" at 180.467,122.555 h1 r90
  text "CAN_L" at 133.477,121.666 h1.5
  text "RFID0" at 154.686,121.539 h1
  text "3V3" at 189.611,119.761 h1
  text "IO2" at 166.751,119.507 h1
  text "GND" at 168.91,119.507 h1
  text "SENSOR" at 171.323,119.507 h1
  text "3V3" at 176.403,119.38 h1
  text "CAN" at 159.131,119.126 h1
  text "SENSOR" at 162.179,119.126 h1
  text "CAN" at 148.082,118.999 h1
  text "3V3" at 171.45,118.491 h1
  text "RF" at 166.878,118.11 h1
  text "RF" at 169.291,118.11 h1
  text "_INT" at 147.828,117.983 h1
  text "MISO" at 156.21,117.856 h1
  text "_CS" at 159.004,117.856 h1
  text "3V3" at 164.084,117.856 h1
  text "SCK" at 150.749,117.729 h1
  text "MOSI" at 153.289,117.729 h1
  text "GND" at 161.671,117.729 h1
  text "IO35" at 173.863,117.602 h1
  text "GND" at 189.611,117.602 h1
  text "GND" at 176.53,117.475 h1
  text "RF1" at 171.45,117.094 h1
  text "ID0" at 166.751,116.967 h1
  text "RST" at 169.037,116.967 h1
  text "TX" at 148.336,116.332 h1
  text "RX" at 150.876,116.332 h1
  text "GND" at 154.432,116.332 h1
  text "3V3" at 156.972,116.332 h1
  text "CAN TX" at 159.512,116.332 h1
  text "MISO" at 163.83,116.332 h1
  text "IO35" at 173.863,116.205 h1
  text "SS" at 171.704,116.078 h1
  text "CAN" at 166.497,115.697 h1
  text "CAN" at 168.91,115.697 h1
  text "LED" at 179.197,115.443 h1
  text "DTR" at 147.955,114.808 h1
  text "RTS" at 150.749,114.808 h1
  text "IO0" at 154.559,114.808 h1
  text "EN" at 157.48,114.808 h1
  text "CAN RX" at 159.512,114.808 h1
  text "MOSI" at 163.83,114.808 h1
  text "GND" at 119.38,114.681 h1
  text "DP" at 122.301,114.681 h1
  text "DN" at 124.841,114.681 h1
  text "5V" at 127.508,114.681 h1
  text "IO12" at 171.45,114.681 h1
  text "IO16" at 173.99,114.681 h1
  text "SW" at 176.784,114.681 h1
  text "SDA" at 181.61,114.681 h1
  text "INT" at 166.751,114.554 h1
  text "CS" at 169.291,114.554 h1
  text "R" at 179.832,114.427 h1
  text "GND" at 186.817,113.157 h1
  text "RE" at 176.911,113.03 h1
  text "LED" at 179.07,113.03 h1
  text "LED" at 181.61,113.03 h1
  text "SCL" at 184.277,113.03 h1
  text "5V" at 189.738,113.03 h1
  text "LAY" at 176.657,111.887 h1
  text "B" at 179.705,111.887 h1
  text "G" at 182.245,111.887 h1
  text "SCK" at 184.277,111.76 h1
  text "GND" at 186.69,111.76 h1
  text "3V3" at 189.357,111.76 h1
